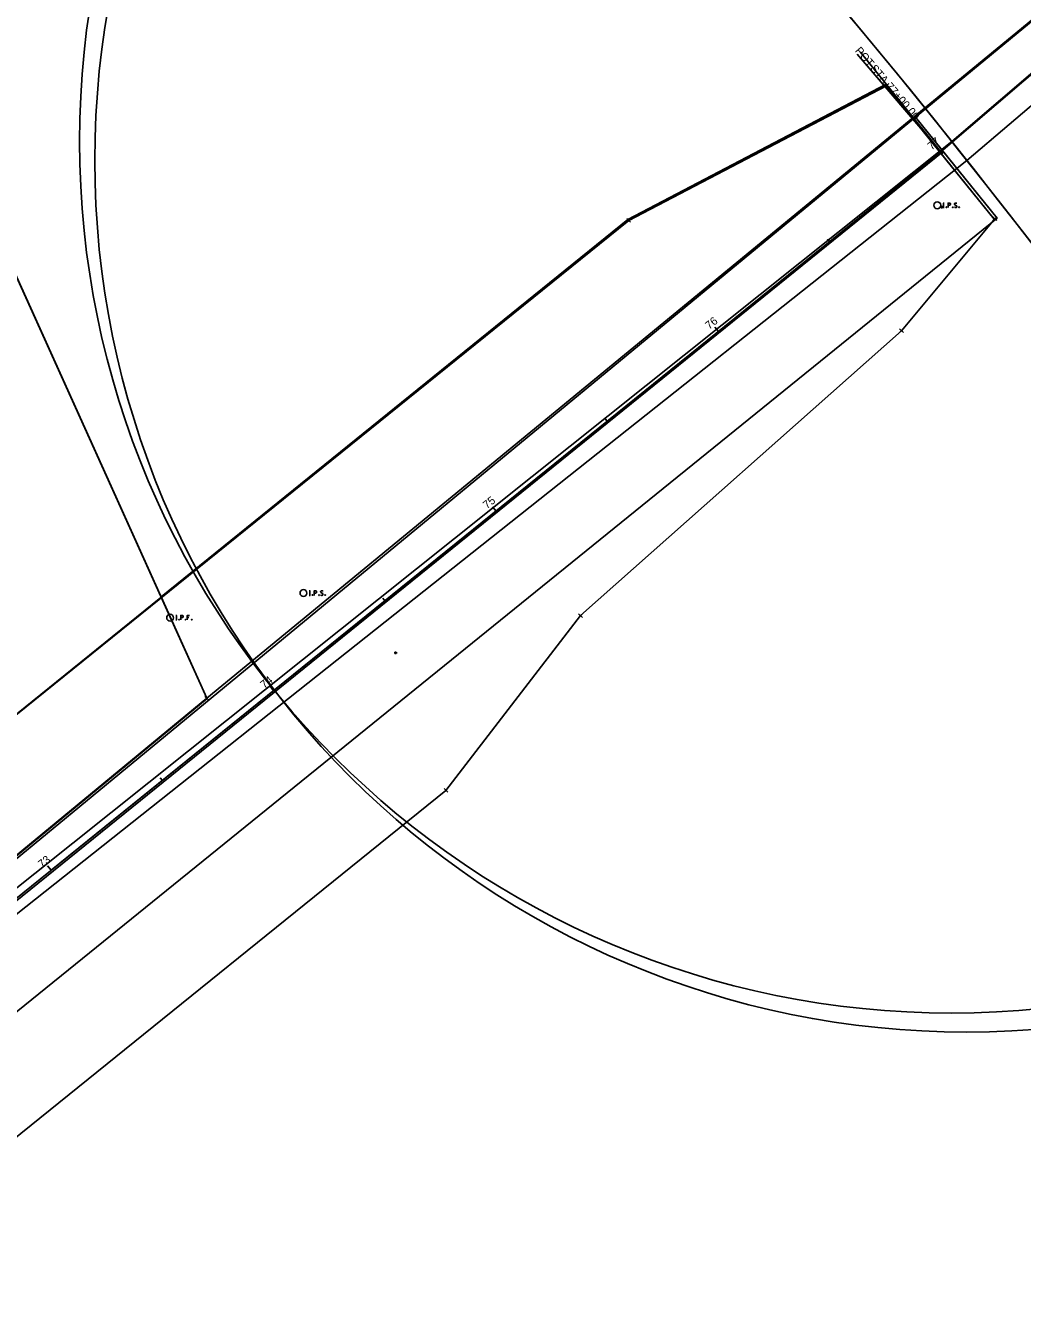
# Model space of a CAD drawing. Extents: x 2180160 to 2188891, y 366108 to 373879.
# Drawn here: x 2185060.8 to 2185409.3, y 370077.2 to 370528.3 of the extents above; entities that cross this region are included whole.
import ezdxf

# ---------------------------------------------------------------- set-up
doc = ezdxf.new("R2010")
doc.units = 0
for name, color, linetype in [('DR_Pond', 7, 'Continuous'), ('GE_P_Alignment', 7, 'Continuous'), ('PV_X_Driveway', 7, 'Continuous'), ('RD_X_Concrete_Pad', 7, 'Continuous'), ('RW_P_Easement_Area', 7, 'Continuous'), ('RW_P_Taking_Area', 7, 'Continuous'), ('RW_X_CL', 7, 'Continuous'), ('SC_Scratch1', 7, 'Continuous'), ('SC_Scratch11', 7, 'Continuous'), ('SC_Scratch4', 7, 'Continuous'), ('SC_Scratch5', 7, 'Continuous'), ('SC_Scratch6', 7, 'Continuous'), ('SC_Scratch8', 7, 'Continuous'), ('SV_P_Control_Cells_Set', 7, 'Continuous'), ('SV_P_Mon_Cells_Set', 7, 'Continuous'), ('SV_X_Mon_Cells_Found', 7, 'Continuous'), ('SV_X_Random_Point', 7, 'Continuous'), ('SV_X_Shot_Marker', 7, 'Continuous')]:
    doc.layers.add(name, color=color, linetype=linetype)

msp = doc.modelspace()

# ---------------------------------------------------------------- linework, layer by layer
at = {"layer": 'DR_Pond'}
for q in [(2185352.64, 370519.17), (2185351.62, 370518.32)]:
    msp.add_line((2185380.91, 370484.16), q, dxfattribs=at)
msp.add_circle((2185380.91, 370484.16), 0.6, dxfattribs=at)
msp.add_circle((2185380.91, 370484.16), 0.6, dxfattribs=at)
at = {"layer": 'GE_P_Alignment'}
for p in [(2184991.92, 370170.03), (2185069.71, 370232.85), (2185069.71, 370232.85)]:
    msp.add_line(p, (2185380.91, 370484.16), dxfattribs=at)
at = {"layer": 'PV_X_Driveway'}
for p, q in [((2185380.91, 370484.16), (2185379.61, 370485.68)), ((2185342.01, 370452.75), (2185341.26, 370453.68)), ((2185303.11, 370421.33), (2185301.86, 370422.89)), ((2185264.21, 370389.92), (2185263.46, 370390.85)), ((2185225.31, 370358.51), (2185224.06, 370360.06)), ((2185186.41, 370327.09), (2185185.66, 370328.03)), ((2185147.51, 370295.68), (2185146.26, 370297.24)), ((2185108.61, 370264.27), (2185107.86, 370265.2)), ((2185069.71, 370232.85), (2185068.46, 370234.41))]:
    msp.add_line(p, q, dxfattribs=at)
at = {"layer": 'RD_X_Concrete_Pad'}
msp.add_line((2185380.91, 370484.16), (2185030.81, 370201.44), dxfattribs=at)
at = {"layer": 'RW_P_Easement_Area'}
for p, q in [((2185124.18, 370293.01), (2185902.93, 370933.53)), ((2184931.61, 370719.54), (2185124.18, 370293.01)), ((2185124.18, 370293.01), (2184905.01, 370111.77))]:
    msp.add_line(p, q, dxfattribs=at)
at = {"layer": 'RW_P_Taking_Area'}
for p, q in [((2185271.7, 370460.23), (2185362.06, 370507.5)), ((2185367.14, 370421.63), (2185399.76, 370460.82)), ((2185038.3, 370271.75), (2185271.7, 370460.23)), ((2185254.84, 370321.94), (2185367.14, 370421.63)), ((2185207.8, 370260.82), (2185254.84, 370321.94)), ((2185056.09, 370138.3), (2185207.8, 370260.82))]:
    msp.add_line(p, q, dxfattribs=at)
at = {"layer": 'RW_X_CL'}
for p, q in [((2185380.91, 370484.16), (2186007.46, 371021.34)), ((2185380.91, 370484.16), (2185902.97, 370931.76)), ((2184660.61, 369902.48), (2185380.91, 370484.16))]:
    msp.add_line(p, q, dxfattribs=at)
at = {"layer": 'SC_Scratch1'}
for points in [[(2185902.93, 370933.53), (2185124.18, 370293.01), (2184997.02, 370187.86), (2184966.35, 370162.49), (2184974.56, 370478.57), (2184967.38, 370202.28), (2184966.35, 370162.49), (2184905.01, 370111.77), (2184906.05, 370151.56), (2184914.22, 370466.4), (2184905.93, 370484.78), (2184971.8, 370484.7), (2184870.37, 370709.34), (2184908.99, 371117.35)], [(2184939.13, 371117.41), (2184900.99, 370714.45), (2185004.74, 370484.66), (2184998.06, 370227.65), (2184997.03, 370187.86), (2185124.18, 370293.01), (2185111.39, 370321.35), (2184931.61, 370719.54), (2184969.27, 371117.49)]]:
    msp.add_lwpolyline(points, dxfattribs=at)
at = {"layer": 'SC_Scratch11'}
msp.add_lwpolyline([(2184427.75, 369717.42), (2184953.09, 370150.77), (2184959.46, 370142.91), (2184915.13, 370107.07), (2185381.71, 370484.31)], dxfattribs=at)
at = {"layer": 'SC_Scratch4'}
msp.add_lwpolyline([(2185898.94, 371118.61), (2185901.45, 370932.63), (2186129.11, 371120.01), (2185370.99, 370496.01), (2185380.69, 370483.98), (2185399.53, 370460.63), (2185361.86, 370507.33), (2185271.47, 370460.11), (2185108.08, 370328.3), (2185037.98, 370271.74), (2184997.75, 370213.58), (2184997.03, 370187.86), (2184952.11, 370150.89), (2184977.3, 370119.66), (2184958.46, 370143.01), (2184952.11, 370150.89), (2184426.3, 369718.09)], dxfattribs=at)
at = {"layer": 'SC_Scratch5'}
for p, q in [((2186133.45, 371128.46), (2185384.67, 370487.88)), ((2186140.76, 371119.43), (2185389.97, 370481.23)), ((2185384.67, 370487.88), (2183283.09, 368809.4)), ((2185389.97, 370481.23), (2183283.09, 368809.4)), ((2185400.59, 370460.97), (2184978.73, 370119.53)), ((2185124.23, 370292.97), (2184427.64, 369717.31))]:
    msp.add_line(p, q, dxfattribs=at)
for points in [[(2185413.22, 370451.5), (2185404.74, 370462.44), (2185396.19, 370473.36), (2185387.57, 370484.25), (2185378.87, 370495.12), (2185370.1, 370505.97), (2185361.26, 370516.78), (2185352.35, 370527.57), (2185343.36, 370538.34)], [(2185417.79, 370445.56), (2185409.31, 370456.57), (2185400.75, 370467.55), (2185392.13, 370478.51), (2185383.43, 370489.44), (2185374.66, 370500.34), (2185365.81, 370511.23), (2185356.9, 370522.08), (2185347.91, 370532.91)], [(2184997.58, 370213.75), (2184996.89, 370188.03), (2184952.01, 370151.01), (2185124.17, 370293.03), (2185108.18, 370328.56), (2185271.42, 370460.55), (2185361.76, 370507.87), (2185370.91, 370496.56)]]:
    msp.add_lwpolyline(points, dxfattribs=at)
for centre in [(2185384.67, 370487.88), (2185389.97, 370481.23)]:
    msp.add_circle(centre, 305, dxfattribs=at)
at = {"layer": 'SC_Scratch6'}
msp.add_lwpolyline([(2185899.27, 371119.5), (2185901.98, 370933.52), (2186129.44, 371121.15), (2185371.99, 370496.33), (2185381.71, 370484.31), (2185400.57, 370460.98), (2185371.99, 370496.33), (2184953.09, 370150.77), (2184427.75, 369717.42), (2184953.09, 370150.77), (2184959.46, 370142.91), (2184915.13, 370107.07), (2185381.71, 370484.31)], dxfattribs=at)
at = {"layer": 'SC_Scratch8'}
msp.add_lwpolyline([(2185898.94, 371118.61), (2185901.45, 370932.63), (2186129.11, 371120.01), (2185370.99, 370496.01), (2185380.69, 370483.98), (2185399.53, 370460.63), (2185361.86, 370507.33), (2185271.47, 370460.11), (2185108.08, 370328.3), (2185037.98, 370271.74), (2184997.75, 370213.58), (2184997.03, 370187.86), (2184952.11, 370150.89), (2184977.3, 370119.66), (2184958.46, 370143.01), (2184952.11, 370150.89), (2184863.14, 370077.66)], dxfattribs=at)
at = {"layer": 'SV_P_Control_Cells_Set'}
for p, q in [((2185123.51, 370292.34), (2185124.84, 370293.67)), ((2185123.51, 370293.67), (2185124.84, 370292.34))]:
    msp.add_line(p, q, dxfattribs=at)
at = {"layer": 'SV_P_Mon_Cells_Set'}
for points in [[(2185381.67, 370466.3), (2185382.02, 370466.3)], [(2185381.84, 370464.7), (2185381.84, 370466.3)], [(2185383.41, 370464.7), (2185383.41, 370466.3), (2185383.94, 370466.3), (2185383.99, 370466.29), (2185384.07, 370466.26), (2185384.1, 370466.24), (2185384.14, 370466.21), (2185384.18, 370466.15), (2185384.21, 370466.09), (2185384.24, 370465.99), (2185384.24, 370465.84), (2185384.23, 370465.79), (2185384.2, 370465.71), (2185384.16, 370465.62), (2185384.11, 370465.58), (2185384.08, 370465.56), (2185384.03, 370465.53), (2185383.94, 370465.52), (2185383.41, 370465.52)], [(2185386.42, 370466.19), (2185386.4, 370466.21), (2185386.36, 370466.24), (2185386.26, 370466.28), (2185386.14, 370466.3), (2185386.05, 370466.3), (2185386.02, 370466.3), (2185385.88, 370466.26), (2185385.76, 370466.19), (2185385.68, 370466.09), (2185385.66, 370465.99), (2185385.66, 370465.91), (2185385.68, 370465.81), (2185385.77, 370465.72), (2185386.37, 370465.34), (2185386.43, 370465.29), (2185386.45, 370465.24), (2185386.47, 370465.17), (2185386.47, 370465.09), (2185386.46, 370465.02), (2185386.45, 370464.97), (2185386.43, 370464.9), (2185386.41, 370464.85), (2185386.39, 370464.82), (2185386.35, 370464.78), (2185386.32, 370464.75), (2185386.28, 370464.73), (2185386.24, 370464.72), (2185386.14, 370464.7), (2185385.99, 370464.7), (2185385.89, 370464.73), (2185385.75, 370464.82), (2185385.66, 370464.89)], [(2185381.67, 370464.7), (2185382.02, 370464.7)], [(2185382.8, 370464.92), (2185382.86, 370464.92), (2185382.89, 370464.89), (2185382.92, 370464.84), (2185382.92, 370464.78), (2185382.89, 370464.73), (2185382.86, 370464.7), (2185382.8, 370464.7), (2185382.77, 370464.73), (2185382.74, 370464.78), (2185382.74, 370464.84), (2185382.77, 370464.89), (2185382.8, 370464.92)], [(2185385.05, 370464.92), (2185385.11, 370464.92), (2185385.14, 370464.89), (2185385.17, 370464.84), (2185385.17, 370464.78), (2185385.14, 370464.73), (2185385.11, 370464.7), (2185385.05, 370464.7), (2185385.02, 370464.73), (2185384.99, 370464.78), (2185384.99, 370464.84), (2185385.02, 370464.89), (2185385.05, 370464.92)], [(2185387.23, 370464.92), (2185387.29, 370464.92), (2185387.32, 370464.89), (2185387.36, 370464.84), (2185387.36, 370464.78), (2185387.32, 370464.73), (2185387.29, 370464.7), (2185387.23, 370464.7), (2185387.2, 370464.73), (2185387.17, 370464.78), (2185387.17, 370464.84), (2185387.2, 370464.89), (2185387.23, 370464.92)], [(2185159.98, 370330.64), (2185160.33, 370330.64)], [(2185160.15, 370329.04), (2185160.15, 370330.64)], [(2185161.72, 370329.04), (2185161.72, 370330.64), (2185162.25, 370330.64), (2185162.3, 370330.63), (2185162.38, 370330.6), (2185162.41, 370330.58), (2185162.45, 370330.55), (2185162.49, 370330.49), (2185162.52, 370330.43), (2185162.55, 370330.33), (2185162.55, 370330.18), (2185162.53, 370330.13), (2185162.51, 370330.05), (2185162.47, 370329.96), (2185162.42, 370329.92), (2185162.39, 370329.9), (2185162.34, 370329.87), (2185162.25, 370329.86), (2185161.72, 370329.86)], [(2185164.73, 370330.53), (2185164.71, 370330.55), (2185164.67, 370330.58), (2185164.57, 370330.62), (2185164.45, 370330.64), (2185164.36, 370330.64), (2185164.33, 370330.64), (2185164.19, 370330.6), (2185164.07, 370330.53), (2185163.99, 370330.43), (2185163.97, 370330.33), (2185163.97, 370330.25), (2185163.99, 370330.15), (2185164.08, 370330.06), (2185164.68, 370329.68), (2185164.74, 370329.63), (2185164.76, 370329.58), (2185164.78, 370329.51), (2185164.78, 370329.43), (2185164.77, 370329.36), (2185164.76, 370329.31), (2185164.74, 370329.24), (2185164.72, 370329.19), (2185164.7, 370329.16), (2185164.66, 370329.12), (2185164.63, 370329.09), (2185164.59, 370329.07), (2185164.55, 370329.05), (2185164.45, 370329.04), (2185164.3, 370329.04), (2185164.2, 370329.07), (2185164.06, 370329.16), (2185163.97, 370329.23)], [(2185159.98, 370329.04), (2185160.33, 370329.04)], [(2185161.11, 370329.26), (2185161.17, 370329.26), (2185161.2, 370329.23), (2185161.23, 370329.18), (2185161.23, 370329.12), (2185161.2, 370329.07), (2185161.17, 370329.04), (2185161.11, 370329.04), (2185161.08, 370329.07), (2185161.05, 370329.12), (2185161.05, 370329.18), (2185161.08, 370329.23), (2185161.11, 370329.26)], [(2185163.36, 370329.26), (2185163.42, 370329.26), (2185163.45, 370329.23), (2185163.48, 370329.18), (2185163.48, 370329.12), (2185163.45, 370329.07), (2185163.42, 370329.04), (2185163.36, 370329.04), (2185163.33, 370329.07), (2185163.3, 370329.12), (2185163.3, 370329.18), (2185163.33, 370329.23), (2185163.36, 370329.26)], [(2185165.54, 370329.26), (2185165.6, 370329.26), (2185165.63, 370329.23), (2185165.67, 370329.18), (2185165.67, 370329.12), (2185165.63, 370329.07), (2185165.6, 370329.04), (2185165.54, 370329.04), (2185165.51, 370329.07), (2185165.48, 370329.12), (2185165.48, 370329.18), (2185165.51, 370329.23), (2185165.54, 370329.26)]]:
    msp.add_lwpolyline(points, dxfattribs=at)
for centre in [(2185379.65, 370465.5), (2185157.96, 370329.84)]:
    msp.add_circle(centre, 1.2, dxfattribs=at)
at = {"layer": 'SV_X_Mon_Cells_Found'}
for points in [[(2185113.32, 370322.02), (2185113.67, 370322.02)], [(2185113.5, 370320.42), (2185113.5, 370322.02)], [(2185115.06, 370320.42), (2185115.06, 370322.02), (2185115.59, 370322.02), (2185115.65, 370322.01), (2185115.73, 370321.99), (2185115.76, 370321.96), (2185115.79, 370321.94), (2185115.84, 370321.87), (2185115.87, 370321.81), (2185115.89, 370321.71), (2185115.89, 370321.56), (2185115.88, 370321.51), (2185115.86, 370321.43), (2185115.81, 370321.34), (2185115.77, 370321.31), (2185115.74, 370321.28), (2185115.68, 370321.26), (2185115.59, 370321.24), (2185115.06, 370321.24)], [(2185118.07, 370322.02), (2185117.31, 370322.02), (2185117.31, 370320.42)], [(2185117.31, 370321.24), (2185117.85, 370321.24)], [(2185113.32, 370320.42), (2185113.67, 370320.42)], [(2185114.46, 370320.64), (2185114.51, 370320.64), (2185114.55, 370320.61), (2185114.58, 370320.56), (2185114.58, 370320.5), (2185114.55, 370320.45), (2185114.51, 370320.42), (2185114.46, 370320.42), (2185114.42, 370320.45), (2185114.39, 370320.5), (2185114.39, 370320.56), (2185114.42, 370320.61), (2185114.46, 370320.64)], [(2185116.71, 370320.64), (2185116.76, 370320.64), (2185116.79, 370320.61), (2185116.83, 370320.56), (2185116.83, 370320.5), (2185116.79, 370320.45), (2185116.76, 370320.42), (2185116.71, 370320.42), (2185116.67, 370320.45), (2185116.64, 370320.5), (2185116.64, 370320.56), (2185116.67, 370320.61), (2185116.71, 370320.64)], [(2185118.86, 370320.64), (2185118.91, 370320.64), (2185118.94, 370320.61), (2185118.98, 370320.56), (2185118.98, 370320.5), (2185118.94, 370320.45), (2185118.91, 370320.42), (2185118.86, 370320.42), (2185118.82, 370320.45), (2185118.79, 370320.5), (2185118.79, 370320.56), (2185118.82, 370320.61), (2185118.86, 370320.64)]]:
    msp.add_lwpolyline(points, dxfattribs=at)
msp.add_circle((2185111.31, 370321.22), 1.2, dxfattribs=at)
at = {"layer": 'SV_X_Random_Point'}
for p, q in [((2185361.4, 370506.83), (2185362.73, 370508.17)), ((2185361.4, 370508.17), (2185362.73, 370506.83)), ((2185380.25, 370483.49), (2185381.58, 370484.83)), ((2185380.25, 370484.83), (2185381.58, 370483.49)), ((2185271.03, 370459.57), (2185272.37, 370460.9)), ((2185271.03, 370460.9), (2185272.37, 370459.57)), ((2185399.09, 370460.15), (2185400.43, 370461.49)), ((2185399.09, 370461.49), (2185400.43, 370460.15)), ((2185366.48, 370420.96), (2185367.81, 370422.3)), ((2185366.48, 370422.3), (2185367.81, 370420.96)), ((2185254.18, 370321.27), (2185255.51, 370322.61)), ((2185254.18, 370322.61), (2185255.51, 370321.27)), ((2185207.13, 370260.15), (2185208.47, 370261.48)), ((2185207.13, 370261.48), (2185208.47, 370260.15))]:
    msp.add_line(p, q, dxfattribs=at)
at = {"layer": 'SV_X_Shot_Marker'}
for p, q in [((2185381.17, 370465.33), (2185381.17, 370464.33)), ((2185380.67, 370464.83), (2185381.67, 370464.83)), ((2185381.17, 370464.83), (2185381.17, 370464.83)), ((2185189.67, 370308.94), (2185190.67, 370308.94)), ((2185190.17, 370309.44), (2185190.17, 370308.44)), ((2185190.17, 370308.94), (2185190.17, 370308.94))]:
    msp.add_line(p, q, dxfattribs=at)

# ---------------------------------------------------------------- texts
at = {"layer": 'DR_Pond'}
for s, p in [('POT', (2185350.68, 370519.47)), (' STA. ', (2185355.32, 370514.06)), ('77+00.00', (2185361.39, 370506.98))]:
    msp.add_text(s, height=2.8, rotation=310.6088, dxfattribs=at).set_placement(p)
at = {"layer": 'PV_X_Driveway'}
for s, rotation, p in [('77', 40.6088, (2185377.67, 370484.68)), ('76', 38.9226, (2185299.88, 370421.94)), ('75', 38.9226, (2185222.12, 370359.14)), ('74', 38.9226, (2185144.26, 370296.27)), ('73', 38.9226, (2185066.52, 370233.49))]:
    msp.add_text(s, height=2.8, rotation=rotation, dxfattribs=at).set_placement(p)

doc.saveas('drawing.dxf')
